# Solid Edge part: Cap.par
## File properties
Author: Vicky Raina
Template: Normal.par
Last saved by: Administrator
Revision: 5
Application: Solid Edge
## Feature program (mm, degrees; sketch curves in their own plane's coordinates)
sketch for "unnamed Protrusion 1" plane through (0, 0, 0) normal (0, -1, 0) x-axis (1, 0, 0)
  line (-54, 0) -> (-54, 12)
  line (-54, 12) -> (-31.749, 12)
  arc centre (0, -24) radius 48 from (-31.749, 12) to (31.749, 12) cw
  line (31.749, 12) -> (54, 12)
  line (54, 12) -> (54, 0)
  line (54, 0) -> (27.6274, 0)
  line (27.6274, -16) -> (27.6274, 0)
  line (22.6274, -16) -> (27.6274, -16)
  arc centre (0, -24) radius 24 from (-22.6274, -16) to (22.6274, -16) cw
  line (-27.6274, -16) -> (-22.6274, -16)
  line (-27.6274, 0) -> (-27.6274, -16)
  line (-27.6274, 0) -> (-54, 0)
  dimension (linear) = 54
extrude "unnamed Protrusion 1" add finite 46 symmetric
sketch for "unnamed Hole 1" plane through (42.8745, 0, 12) normal (0, 0, 1) x-axis (0, 1, 0)
hole "unnamed Hole 1" through
sketch for "unnamed Cutout 1" plane through (42.8745, 0, 12) normal (0, 0, 1) x-axis (0, 1, 0)
extrude "unnamed Cutout 1" cut through along +normal
sketch for "unnamed Cutout 2" plane through (38, 0, 12) normal (0, 0, 1) x-axis (0, 1, 0)
  line (-23, -16) -> (-23, -10.8569)
  arc centre (0, 38) radius 54 from (23, -10.8569) to (-23, -10.8569) cw
  line (23, -16) -> (23, -10.8569)
  line (1.0714, -23.7143) -> (23, -16)
  line (-23, -16) -> (1.0714, -23.7143)
extrude "unnamed Cutout 2" cut through along -normal
mirror "unnamed Mirror 1" of "unnamed Cutout 2", "unnamed Cutout 1", "unnamed Hole 1" about plane through (0, 0, 0) normal (1, 0, 0)
hole "unnamed Hole 2" through
extrude "unnamed Cutout 3" cut through
extrude "unnamed Cutout 4" cut through
sketch for "unnamed Hole 3" plane through (25.1274, 0, 24) normal (0, 0, -1) x-axis (0, 1, 0)
  hole centre (0, -25.1274) bore radius 3
hole "unnamed Hole 3" through
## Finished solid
Body 1: solid body, 21 faces, 50 edges, 28 vertices.
  Faces by surface: plane 11, cylinder 10
  Edges by curve: line 30, circle 16, intersection 4
Bounding box of the edges (mm): 108.000 x 46.000 x 40.000, from (-54, -23, -16) to (54, 23, 24).
Cylindrical faces by radius (mm): R3 x1, R4 x1, R6 x2, R17 x2, R24 x1, R48 x1, R54 x2
Planar faces by outward normal: +x 1, +y 1, +z 3, -x 1, -y 1, -z 4
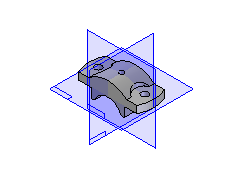
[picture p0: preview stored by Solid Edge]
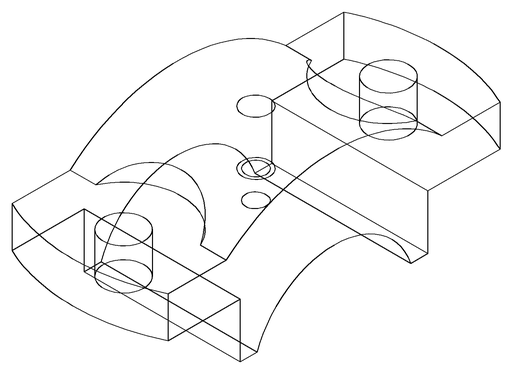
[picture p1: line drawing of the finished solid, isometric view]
